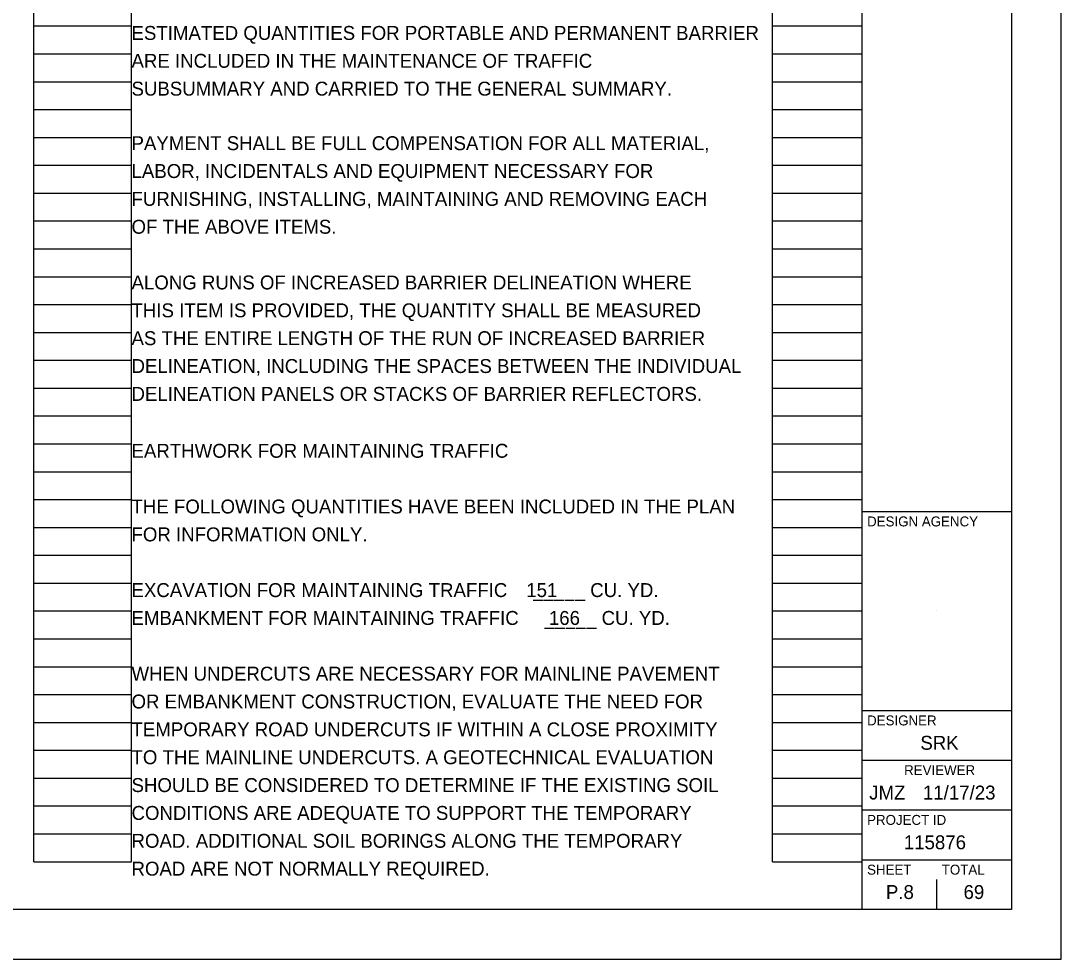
# Model space of a CAD drawing. Extents: x 0 to 40, y 0 to 22.
# Drawn here: x 23.55 to 34, y 0 to 9.43 of the extents above; entities that cross this region are included whole.
import ezdxf

# ---------------------------------------------------------------- set-up
doc = ezdxf.new("R2010")
doc.units = 0
for name, color, linetype in [('SH_Border', 7, 'Continuous'), ('SH_Cut_Line', 7, 'Continuous'), ('SH_Data', 7, 'Continuous'), ('SH_Text', 7, 'Continuous')]:
    doc.layers.add(name, color=color, linetype=linetype)

msp = doc.modelspace()

# ---------------------------------------------------------------- linework, layer by layer
at = {"layer": 'SH_Border'}
for p, q in [((32, 0.5), (32, 21.5)), ((32, 4.5), (33.5, 4.5)), ((32, 2.5), (33.5, 2.5)), ((32, 2), (33.5, 2)), ((32, 1.5), (33.5, 1.5)), ((32, 1), (33.5, 1))]:
    msp.add_line(p, q, dxfattribs=at)
msp.add_lwpolyline([(1.5, 21.5), (33.5, 21.5), (33.5, 0.5), (1.5, 0.5)], close=True, dxfattribs=at)
at = {"layer": 'SH_Cut_Line'}
msp.add_lwpolyline([(0, 0), (34, 0), (34, 22), (0, 22)], close=True, dxfattribs=at)
at = {"layer": 'SH_Data'}
for p, q in [((23.68, 0.98), (23.68, 21.14)), ((24.66, 0.98), (24.66, 21.14)), ((31.1, 0.98), (31.1, 21.14)), ((32, 0.98), (32, 21.14)), ((23.68, 9.38), (24.66, 9.38)), ((31.1, 9.38), (32, 9.38)), ((23.68, 9.1), (24.66, 9.1)), ((31.1, 9.1), (32, 9.1)), ((23.68, 8.82), (24.66, 8.82)), ((31.1, 8.82), (32, 8.82)), ((23.68, 8.54), (24.66, 8.54)), ((31.1, 8.54), (32, 8.54)), ((23.68, 8.26), (24.66, 8.26)), ((31.1, 8.26), (32, 8.26)), ((23.68, 7.98), (24.66, 7.98)), ((31.1, 7.98), (32, 7.98)), ((23.68, 7.7), (24.66, 7.7)), ((31.1, 7.7), (32, 7.7)), ((23.68, 7.42), (24.66, 7.42)), ((31.1, 7.42), (32, 7.42)), ((23.68, 7.14), (24.66, 7.14)), ((31.1, 7.14), (32, 7.14)), ((23.68, 6.86), (24.66, 6.86)), ((31.1, 6.86), (32, 6.86)), ((23.68, 6.58), (24.66, 6.58)), ((31.1, 6.58), (32, 6.58)), ((23.68, 6.3), (24.66, 6.3)), ((31.1, 6.3), (32, 6.3)), ((23.68, 6.02), (24.66, 6.02)), ((31.1, 6.02), (32, 6.02)), ((23.68, 5.74), (24.66, 5.74)), ((31.1, 5.74), (32, 5.74)), ((23.68, 5.46), (24.66, 5.46)), ((31.1, 5.46), (32, 5.46)), ((23.68, 5.18), (24.66, 5.18)), ((31.1, 5.18), (32, 5.18)), ((23.68, 4.9), (24.66, 4.9)), ((31.1, 4.9), (32, 4.9)), ((23.68, 4.62), (24.66, 4.62)), ((31.1, 4.62), (32, 4.62)), ((23.68, 4.34), (24.66, 4.34)), ((31.1, 4.34), (32, 4.34)), ((23.68, 4.06), (24.66, 4.06)), ((31.1, 4.06), (32, 4.06)), ((23.68, 3.78), (24.66, 3.78)), ((31.1, 3.78), (32, 3.78)), ((23.68, 3.5), (24.66, 3.5)), ((31.1, 3.5), (32, 3.5)), ((32.75, 3.5), (32.75, 3.5)), ((23.68, 3.22), (24.66, 3.22)), ((31.1, 3.22), (32, 3.22)), ((23.68, 2.94), (24.66, 2.94)), ((31.1, 2.94), (32, 2.94)), ((23.68, 2.66), (24.66, 2.66)), ((31.1, 2.66), (32, 2.66)), ((23.68, 2.38), (24.66, 2.38)), ((31.1, 2.38), (32, 2.38)), ((23.68, 2.1), (24.66, 2.1)), ((31.1, 2.1), (32, 2.1)), ((23.68, 1.82), (24.66, 1.82)), ((31.1, 1.82), (32, 1.82)), ((23.68, 1.54), (24.66, 1.54)), ((31.1, 1.54), (32, 1.54)), ((23.68, 1.26), (24.66, 1.26)), ((31.1, 1.26), (32, 1.26)), ((23.68, 0.98), (24.66, 0.98)), ((31.1, 0.98), (32, 0.98)), ((32.75, 0.5), (32.75, 0.8)), ((32.375, 0.675), (32.375, 0.675))]:
    msp.add_line(p, q, dxfattribs=at)

# ---------------------------------------------------------------- texts
for s, height, p in [('DESIGN AGENCY', 0.1, (32.05, 4.35)), ('DESIGNER', 0.1, (32.05, 2.35)), ('SRK', 0.14, (32.585, 2.105)), ('REVIEWER', 0.1, (32.422, 1.85)), ('JMZ', 0.14, (32.071, 1.605)), ('11/17/23', 0.14, (32.611, 1.605)), ('PROJECT ID', 0.1, (32.05, 1.35)), ('115876', 0.14, (32.419, 1.105)), ('SHEET', 0.1, (32.05, 0.85)), ('TOTAL', 0.1, (32.8, 0.85)), ('P.8', 0.14, (32.239, 0.605)), ('69', 0.14, (33.019, 0.605))]:
    msp.add_text(s, height=height, dxfattribs=at).set_placement(p)
at = {"layer": 'SH_Text'}
for s, p in [('ESTIMATED QUANTITIES FOR PORTABLE AND PERMANENT BARRIER', (24.66, 9.24)), ('ARE INCLUDED IN THE MAINTENANCE OF TRAFFIC', (24.66, 8.96)), ('SUBSUMMARY AND CARRIED TO THE GENERAL SUMMARY.', (24.66, 8.68)), ('PAYMENT SHALL BE FULL COMPENSATION FOR ALL MATERIAL,', (24.66, 8.132)), ('LABOR, INCIDENTALS AND EQUIPMENT NECESSARY FOR', (24.66, 7.852)), ('FURNISHING, INSTALLING, MAINTAINING AND REMOVING EACH', (24.66, 7.572)), ('OF THE ABOVE ITEMS.', (24.66, 7.292)), ('ALONG RUNS OF INCREASED BARRIER DELINEATION WHERE', (24.66, 6.732)), ('THIS ITEM IS PROVIDED, THE QUANTITY SHALL BE MEASURED', (24.66, 6.452)), ('AS THE ENTIRE LENGTH OF THE RUN OF INCREASED BARRIER', (24.66, 6.172)), ('DELINEATION, INCLUDING THE SPACES BETWEEN THE INDIVIDUAL', (24.66, 5.892)), ('DELINEATION PANELS OR STACKS OF BARRIER REFLECTORS.', (24.66, 5.612)), ('EARTHWORK FOR MAINTAINING TRAFFIC', (24.66, 5.04)), ('THE FOLLOWING QUANTITIES HAVE BEEN INCLUDED IN THE PLAN', (24.66, 4.48)), ('FOR INFORMATION ONLY.', (24.66, 4.2)), ('EXCAVATION FOR MAINTAINING TRAFFIC     _____ CU. YD.', (24.66, 3.64)), ('151', (28.626, 3.64)), ('EMBANKMENT FOR MAINTAINING TRAFFIC     _____ CU. YD.', (24.66, 3.36)), ('166', (28.853, 3.36)), ('WHEN UNDERCUTS ARE NECESSARY FOR MAINLINE PAVEMENT', (24.66, 2.8)), ('OR EMBANKMENT CONSTRUCTION, EVALUATE THE NEED FOR', (24.66, 2.52)), ('TEMPORARY ROAD UNDERCUTS IF WITHIN A CLOSE PROXIMITY', (24.66, 2.24)), ('TO THE MAINLINE UNDERCUTS. A GEOTECHNICAL EVALUATION', (24.66, 1.96)), ('SHOULD BE CONSIDERED TO DETERMINE IF THE EXISTING SOIL', (24.66, 1.68)), ('CONDITIONS ARE ADEQUATE TO SUPPORT THE TEMPORARY', (24.66, 1.4)), ('ROAD. ADDITIONAL SOIL BORINGS ALONG THE TEMPORARY', (24.66, 1.12)), ('ROAD ARE NOT NORMALLY REQUIRED.', (24.66, 0.84))]:
    msp.add_text(s, height=0.14, dxfattribs=at).set_placement(p)

doc.saveas('drawing.dxf')
